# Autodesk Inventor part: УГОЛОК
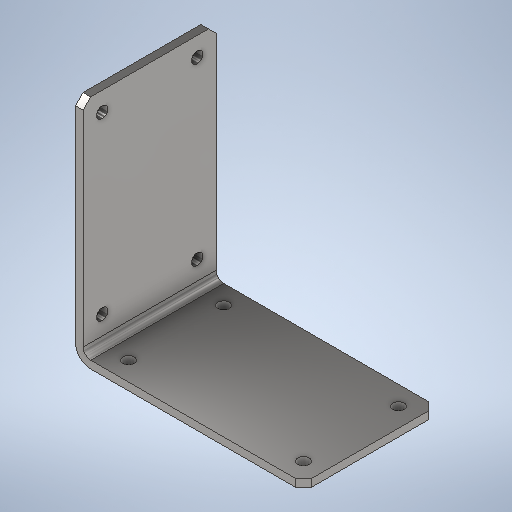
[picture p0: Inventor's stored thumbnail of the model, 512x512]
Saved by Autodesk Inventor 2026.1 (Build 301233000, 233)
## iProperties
Created: 2025-12
Part Number: УГОЛОК
Material: Типовые
Document SubType Name: Modeling
Designer: Yury Melnikov
Density: 1 g/cm^3
Appearance: Сталь — полированная
Author: Yury Melnikov
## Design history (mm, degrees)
sketch "Эскиз1"
  geometry: L1 (0, 60)-(0, 4); L2 (4, 0)-(60, 0); L3 (2, 60)-(2, 4); L4 (4, 2)-(60, 2); L5 (60, 2)-(60, 0); L6 (2, 60)-(0, 60); A1 r 2 centre (4, 4) between (2, 4) and (4, 2); A2 r 4 centre (4, 4) between (0, 4) and (4, 0); 1 further point
  constraints: 12 end point, 4 perpendicular, 4 point on circle, 4 tangent, 2 centre point, 2 point on line, 2 vertical, 1 concentric, 1 horizontal alignment, 1 vertical alignment, 1 other
  dimensions: "d0" = 2 distance between parallel lines of L1 L3; "d1" = 60 distance of L1.start point (0, 0); "d3" = 2 radius of A1
extrude "Выдавливание1" new body sketch "Эскиз1" distance "d4" = 35; taper "d5" = 0 deg
sketch "Эскиз2"
  geometry: L1 (0, 0)-(0, 56) reference; L2 (0, 56)-(-35, 56) reference; L3 (-35, 0)-(-35, 56) reference; L4 (0, 0)-(-35, 0) reference; L5 (-30, 51)-(-5, 51); L6 (-5, 51)-(-5, 5); L7 (-5, 5)-(-30, 5); L8 (-30, 5)-(-30, 51); C1 r 1.5 at (-30, 51); C2 r 1.5 at (-5, 51); C3 r 1.5 at (-5, 5); C4 r 1.5 at (-30, 5); 1 further point
  constraints: 8 end point, 4 centre point, 4 coincident, 3 equal radius, 3 other
  dimensions: "d6" = 3 diameter of C2; "d7" = 5 distance between parallel lines of L1 L6
extrude "Выдавливание2" cut sketch "Эскиз2" distance "d8" = 35; taper "d9" = 0 deg
pattern_circular "Круговой массив1" dims angle "d11" = 360 deg
chamfer "Фаска1" distance "d13" = 2; stored, may be unused: second distance "d14" = 2, angle "d15" = 45 deg
node "Твердое тело1"
node "Спроецированная петля1"
